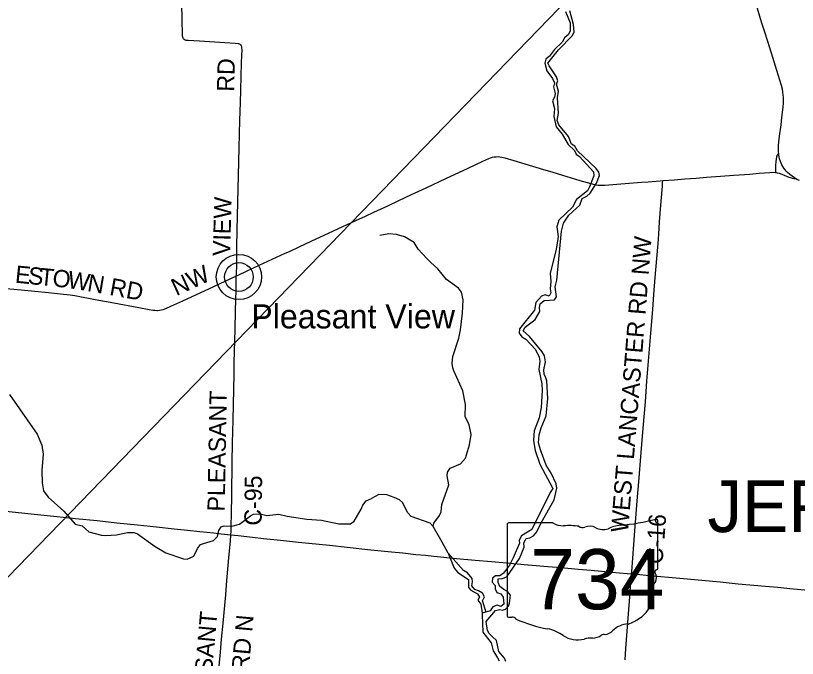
# Model space of a CAD drawing. Extents: x -49 to -8.2, y 9.4 to 23.5.
# Drawn here: x -41.967 to -40.683, y 18.399 to 19.456 of the extents above; entities that cross this region are included whole.
import ezdxf

# ---------------------------------------------------------------- set-up
doc = ezdxf.new("R2010")
doc.units = 0
for name, color, linetype in [('GM_X_County_Road', 7, 'Continuous'), ('GM_X_County_Road_Text', 7, 'Continuous'), ('GM_X_Major_River', 7, 'Continuous'), ('GM_X_Minor_River', 7, 'Continuous'), ('GM_X_State_Route', 7, 'Continuous'), ('GM_X_State_Shield', 7, 'Continuous'), ('GM_X_Township_Text', 7, 'Continuous'), ('GM_X_Unincorporated', 7, 'Continuous'), ('GM_X_Unincorporated_Text', 7, 'Continuous'), ('SC_Scratch1', 7, 'Continuous')]:
    doc.layers.add(name, color=color, linetype=linetype)

msp = doc.modelspace()

# ---------------------------------------------------------------- linework, layer by layer
at = {"layer": 'GM_X_County_Road'}
for points in [[(-41.6048, 19.0281), (-41.6042, 19.0488), (-41.6038, 19.0767), (-41.6027, 19.1264), (-41.6011, 19.1932), (-41.6, 19.2382), (-41.5994, 19.2615), (-41.599, 19.2833), (-41.5982, 19.3128), (-41.5976, 19.3329), (-41.5969, 19.3562), (-41.5962, 19.378), (-41.5958, 19.3904), (-41.5955, 19.3997), (-41.5956, 19.4027), (-41.5958, 19.4042), (-41.5963, 19.4056), (-41.5969, 19.4069), (-41.5979, 19.4079), (-41.5991, 19.4087), (-41.6005, 19.4092), (-41.602, 19.4095), (-41.6066, 19.41), (-41.6236, 19.411), (-41.6655, 19.4135), (-41.6841, 19.4146), (-41.6857, 19.4147), (-41.6873, 19.415), (-41.6888, 19.4155), (-41.6903, 19.4163), (-41.6915, 19.4174), (-41.6924, 19.4188), (-41.6929, 19.4203), (-41.6932, 19.4219), (-41.6934, 19.4251), (-41.6937, 19.4484), (-41.6946, 19.4763)], [(-40.7186, 19.198), (-40.7186, 19.2018), (-40.7186, 19.2049), (-40.7184, 19.2095), (-40.7179, 19.2157), (-40.7169, 19.2234), (-40.7165, 19.2252), (-40.7162, 19.2264), (-40.7155, 19.2276), (-40.7148, 19.2284), (-40.7138, 19.2292)], [(-41.6048, 19.0281), (-41.5996, 19.0305), (-41.5671, 19.0454), (-41.5247, 19.0651), (-41.5177, 19.0683), (-41.5015, 19.0758), (-41.4817, 19.085), (-41.445, 19.1019), (-41.4084, 19.1189), (-41.3929, 19.1261), (-41.3788, 19.1326), (-41.3562, 19.143), (-41.3379, 19.1516), (-41.3169, 19.1616), (-41.293, 19.1728), (-41.2605, 19.1879), (-41.2239, 19.205), (-41.2001, 19.2163), (-41.1901, 19.2207), (-41.1872, 19.2218), (-41.1842, 19.2228), (-41.1811, 19.2235), (-41.178, 19.2238), (-41.1748, 19.2239), (-41.1717, 19.2237), (-41.1686, 19.2232), (-41.164, 19.2222), (-41.1491, 19.2178), (-41.1, 19.2029), (-41.0866, 19.1988), (-41.0688, 19.1934), (-41.0405, 19.1849), (-41.0226, 19.1797), (-41.0166, 19.1781), (-41.0136, 19.1775), (-41.0106, 19.1772), (-41.0059, 19.1771), (-40.9997, 19.1773), (-40.9796, 19.1789), (-40.9595, 19.1804), (-40.9393, 19.1819), (-40.9285, 19.1828), (-40.9084, 19.1842), (-40.904, 19.1846)], [(-40.904, 19.1846), (-40.8851, 19.1859), (-40.8681, 19.1872), (-40.8495, 19.1888), (-40.8324, 19.1901), (-40.8092, 19.1918), (-40.7875, 19.1934), (-40.7612, 19.1954), (-40.7457, 19.1966), (-40.7286, 19.1979), (-40.7224, 19.1982), (-40.7193, 19.1981), (-40.7186, 19.198)], [(-40.7186, 19.198), (-40.7177, 19.1979), (-40.7161, 19.1976), (-40.7131, 19.1968), (-40.7087, 19.1951), (-40.6972, 19.1904), (-40.6942, 19.1894), (-40.6919, 19.1887), (-40.6888, 19.1881), (-40.6863, 19.1878)], [(-40.9556, 18.5385), (-40.9553, 18.5425), (-40.9535, 18.5642), (-40.9499, 18.6091), (-40.9478, 18.6369), (-40.9461, 18.6586), (-40.9436, 18.6895), (-40.9396, 18.7375), (-40.9363, 18.7778), (-40.9329, 18.8211), (-40.9302, 18.8551), (-40.9281, 18.8815), (-40.9259, 18.9078), (-40.9239, 18.9341), (-40.9208, 18.9728), (-40.9189, 18.9976), (-40.9168, 19.0254), (-40.9142, 19.0564), (-40.9121, 19.0811), (-40.911, 19.0966), (-40.9095, 19.1167), (-40.9084, 19.1307), (-40.9068, 19.1508), (-40.9049, 19.1755), (-40.9045, 19.1802), (-40.904, 19.1846)], [(-41.9892, 19.0078), (-41.9583, 19.0049), (-41.9134, 19.0006), (-41.8887, 18.9981), (-41.8779, 18.9968), (-41.8702, 18.9955), (-41.8366, 18.9892), (-41.8061, 18.9835), (-41.7648, 18.9758), (-41.748, 18.9727), (-41.7419, 18.9717), (-41.7388, 18.9714), (-41.7357, 18.9712), (-41.7342, 18.9713), (-41.7312, 18.9716), (-41.7282, 18.9721), (-41.7252, 18.973), (-41.7209, 18.9745), (-41.7123, 18.9782), (-41.6925, 18.9872), (-41.6418, 19.0108), (-41.6221, 19.02), (-41.6048, 19.0281)], [(-41.6138, 18.6026), (-41.6134, 18.6077), (-41.6132, 18.617), (-41.6128, 18.6372), (-41.6125, 18.6683), (-41.6117, 18.7211), (-41.6111, 18.7537), (-41.6103, 18.791), (-41.6086, 18.8671), (-41.6082, 18.8857), (-41.607, 18.9401), (-41.6062, 18.9711), (-41.6053, 19.0053), (-41.6049, 19.027), (-41.6048, 19.0281)], [(-41.6386, 18.3226), (-41.6375, 18.3354), (-41.6339, 18.3756), (-41.6309, 18.4097), (-41.629, 18.4313), (-41.6266, 18.4576), (-41.6223, 18.504), (-41.6203, 18.5272), (-41.6165, 18.5706), (-41.6145, 18.5922), (-41.6138, 18.6026)], [(-40.9663, 18.397), (-40.9649, 18.4156), (-40.9606, 18.4728), (-40.9584, 18.5007), (-40.9571, 18.5177), (-40.9556, 18.5385)]]:
    msp.add_lwpolyline(points, dxfattribs=at)
at = {"layer": 'GM_X_Major_River'}
for points in [[(-41.0642, 19.4627), (-41.0565, 19.4439), (-41.0566, 19.4308), (-41.0591, 19.4248), (-41.0655, 19.4191), (-41.0694, 19.4119), (-41.0823, 19.4002), (-41.0903, 19.3889), (-41.0964, 19.3841), (-41.0979, 19.3773), (-41.095, 19.3652), (-41.0852, 19.3522), (-41.0824, 19.3454), (-41.0836, 19.3389), (-41.081, 19.3279), (-41.0819, 19.3218), (-41.0856, 19.3158), (-41.082, 19.3031), (-41.0834, 19.2898), (-41.0795, 19.2731), (-41.0694, 19.2611), (-41.0598, 19.244), (-41.0491, 19.234), (-41.0468, 19.2278), (-41.0408, 19.2241), (-41.0182, 19.1992), (-41.0177, 19.1925), (-41.0246, 19.1742), (-41.0277, 19.1677), (-41.0459, 19.1534), (-41.0526, 19.1409), (-41.0752, 19.1198), (-41.0781, 19.1086), (-41.0759, 19.0925), (-41.0795, 19.0714), (-41.0895, 19.0322), (-41.0883, 19.0187), (-41.0893, 19.0066), (-41.088, 19.0001), (-41.0908, 18.9945), (-41.0977, 18.9966), (-41.1037, 18.9949), (-41.113, 18.9843), (-41.115, 18.9718), (-41.1396, 18.9412), (-41.14, 18.934), (-41.1357, 18.9279), (-41.1295, 18.9241), (-41.1133, 18.907), (-41.1071, 18.8944), (-41.1062, 18.8881), (-41.1078, 18.8743), (-41.1031, 18.8506), (-41.1024, 18.8394), (-41.1041, 18.8117), (-41.1074, 18.7948), (-41.1153, 18.7734), (-41.1165, 18.7585), (-41.1163, 18.7535), (-41.1138, 18.741), (-41.1061, 18.7188), (-41.0849, 18.6788), (-41.0895, 18.672), (-41.1194, 18.6113), (-41.1366, 18.6006), (-41.1401, 18.5938), (-41.1399, 18.589), (-41.1499, 18.5646), (-41.156, 18.5529), (-41.1659, 18.5393), (-41.1722, 18.5351), (-41.1788, 18.535), (-41.1839, 18.531), (-41.1845, 18.5249), (-41.1796, 18.5194), (-41.1797, 18.5139), (-41.1771, 18.5078), (-41.1703, 18.5057), (-41.1667, 18.5002), (-41.1654, 18.4884), (-41.1704, 18.4847), (-41.1762, 18.487), (-41.1832, 18.4842), (-41.1878, 18.4775), (-41.2011, 18.4735)], [(-41.0957, 18.7172), (-41.1054, 18.7419), (-41.1082, 18.7539), (-41.1074, 18.7669), (-41.1043, 18.7783), (-41.0959, 18.798), (-41.0931, 18.8264), (-41.0946, 18.8557), (-41.0965, 18.8604), (-41.0989, 18.8663), (-41.0998, 18.8737), (-41.0969, 18.8868), (-41.0987, 18.8964), (-41.1025, 18.9031), (-41.1234, 18.9282), (-41.1337, 18.9378), (-41.1301, 18.9438), (-41.1252, 18.9476), (-41.1187, 18.9523), (-41.114, 18.9561), (-41.1061, 18.9695), (-41.107, 18.9758), (-41.1055, 18.982), (-41.0992, 18.9873), (-41.0822, 18.9887), (-41.0791, 18.9937), (-41.0809, 19.0098), (-41.0784, 19.0208), (-41.0704, 19.1014), (-41.0675, 19.1148), (-41.0585, 19.1279), (-41.0407, 19.1441), (-41.0366, 19.1551), (-41.0289, 19.1588), (-41.0233, 19.1639), (-41.0134, 19.1804), (-41.0082, 19.1932), (-41.0095, 19.1982), (-41.0137, 19.2043), (-41.0444, 19.2336), (-41.0487, 19.2409), (-41.0541, 19.2443), (-41.0594, 19.2572), (-41.075, 19.2761), (-41.0776, 19.2831), (-41.0766, 19.2896), (-41.0755, 19.2954), (-41.077, 19.3207), (-41.0753, 19.3317), (-41.0786, 19.3431), (-41.0767, 19.3486), (-41.0789, 19.3552), (-41.0911, 19.3729), (-41.093, 19.3777), (-41.0755, 19.3994), (-41.0524, 19.423), (-41.0496, 19.4291), (-41.0507, 19.4412), (-41.0568, 19.4636)], [(-41.1619, 18.3945), (-41.1644, 18.3997), (-41.1736, 18.4109), (-41.1775, 18.4286), (-41.1841, 18.435), (-41.1897, 18.4404), (-41.1921, 18.4451), (-41.1945, 18.4603), (-41.1789, 18.4779), (-41.1725, 18.4797), (-41.1676, 18.4788), (-41.1628, 18.4801), (-41.1579, 18.4854), (-41.1559, 18.4903), (-41.1542, 18.5032), (-41.1593, 18.5096), (-41.1655, 18.5127), (-41.1717, 18.5177), (-41.1747, 18.5241), (-41.1749, 18.53), (-41.1682, 18.5305), (-41.1606, 18.5335), (-41.1399, 18.5638), (-41.132, 18.5821), (-41.1325, 18.5895), (-41.1285, 18.5965), (-41.1225, 18.5977), (-41.1164, 18.6008), (-41.1109, 18.6076), (-41.1043, 18.6222), (-41.0828, 18.6599), (-41.0781, 18.6792), (-41.0796, 18.6864), (-41.0876, 18.7039), (-41.0957, 18.7172)], [(-41.2011, 18.4735), (-41.2009, 18.4708), (-41.1997, 18.4425), (-41.1862, 18.425), (-41.1827, 18.4119), (-41.1789, 18.4056), (-41.1759, 18.4001), (-41.1733, 18.3952)]]:
    msp.add_lwpolyline(points, dxfattribs=at)
at = {"layer": 'GM_X_Minor_River'}
for points in [[(-41.2814, 18.6161), (-41.2804, 18.6219), (-41.2708, 18.6342), (-41.2685, 18.6401), (-41.2672, 18.6522), (-41.2558, 18.6848), (-41.2586, 18.6996), (-41.2578, 18.7057), (-41.2538, 18.7119), (-41.2365, 18.7194), (-41.2285, 18.7287), (-41.2218, 18.7502), (-41.2192, 18.7673), (-41.2226, 18.7834), (-41.2287, 18.7969), (-41.2281, 18.8169), (-41.2327, 18.8393), (-41.2475, 18.8718), (-41.2491, 18.8767), (-41.2504, 18.8841), (-41.2492, 18.8955), (-41.2394, 18.9254), (-41.2363, 18.9394), (-41.2331, 18.9669), (-41.2321, 18.9887), (-41.235, 19.0012), (-41.2399, 19.0077), (-41.2594, 19.022), (-41.2736, 19.0396), (-41.2851, 19.0502), (-41.2921, 19.0565), (-41.306, 19.072), (-41.3126, 19.0826), (-41.3288, 19.0924), (-41.3419, 19.0958), (-41.3544, 19.0972), (-41.3689, 19.0945)], [(-41.9773, 18.833), (-41.9319, 18.7678), (-41.9245, 18.7497), (-41.9224, 18.7351), (-41.9246, 18.7082), (-41.924, 18.6879), (-41.9215, 18.6747), (-41.9138, 18.6646), (-41.8885, 18.6416), (-41.8698, 18.62), (-41.8581, 18.6172), (-41.847, 18.6074), (-41.8261, 18.6017), (-41.8194, 18.6012), (-41.8016, 18.6026), (-41.7834, 18.6064), (-41.7727, 18.6061), (-41.7674, 18.604), (-41.7383, 18.5834), (-41.7204, 18.5731), (-41.6915, 18.5632), (-41.6855, 18.5627), (-41.6749, 18.5672), (-41.6687, 18.5802), (-41.6635, 18.5864), (-41.6588, 18.5885), (-41.6421, 18.593), (-41.636, 18.5996), (-41.6336, 18.6095), (-41.6296, 18.6157), (-41.6248, 18.6175), (-41.6123, 18.6165), (-41.5998, 18.6201), (-41.5815, 18.6336), (-41.5766, 18.6362), (-41.5658, 18.6369), (-41.5549, 18.6341), (-41.535, 18.6364), (-41.5214, 18.633), (-41.4889, 18.6283), (-41.4647, 18.6266), (-41.4367, 18.6208), (-41.4171, 18.6206), (-41.4114, 18.6251), (-41.4, 18.6445), (-41.3969, 18.6515), (-41.3917, 18.6583), (-41.3828, 18.6623)], [(-41.2566, 18.5721), (-41.2669, 18.5904), (-41.2814, 18.6161), (-41.2862, 18.6218), (-41.3174, 18.6324), (-41.3229, 18.6385), (-41.3321, 18.6558), (-41.337, 18.6598), (-41.3455, 18.664), (-41.3577, 18.6682), (-41.371, 18.6685), (-41.3828, 18.6623)], [(-41.1945, 18.4756), (-41.2004, 18.4939), (-41.1972, 18.5007), (-41.2003, 18.5066), (-41.2068, 18.5103), (-41.2132, 18.5129), (-41.2179, 18.5185), (-41.2167, 18.5253), (-41.2176, 18.5306), (-41.2252, 18.5403), (-41.2319, 18.5441), (-41.2566, 18.5721)], [(-41.2566, 18.5721), (-41.2467, 18.5476), (-41.2412, 18.5406), (-41.2233, 18.5291), (-41.2236, 18.5162), (-41.2196, 18.5113), (-41.2085, 18.5053), (-41.2053, 18.4998), (-41.2082, 18.4949), (-41.2033, 18.4884), (-41.2011, 18.4735)]]:
    msp.add_lwpolyline(points, dxfattribs=at)
at = {"layer": 'GM_X_State_Route'}
for points in [[(-40.6798, 19.1845), (-40.684, 19.1866), (-40.6863, 19.1878), (-40.6881, 19.189), (-40.6919, 19.1916), (-40.6956, 19.1946), (-40.6991, 19.1977), (-40.7013, 19.1999), (-40.7033, 19.2023), (-40.7052, 19.2049), (-40.7069, 19.2075), (-40.7084, 19.2103), (-40.7097, 19.2131), (-40.7109, 19.216), (-40.7123, 19.2205), (-40.713, 19.2236), (-40.7135, 19.2266), (-40.7138, 19.2292), (-40.714, 19.2313), (-40.7141, 19.236), (-40.7139, 19.2422), (-40.7135, 19.2485), (-40.7124, 19.2577), (-40.7099, 19.2762), (-40.7084, 19.2885), (-40.7065, 19.3055), (-40.7059, 19.3117), (-40.7057, 19.3163), (-40.7058, 19.321), (-40.7062, 19.3256), (-40.7068, 19.3301), (-40.7077, 19.3347), (-40.7093, 19.3407), (-40.7147, 19.3585), (-40.7235, 19.3867), (-40.7286, 19.403), (-40.7361, 19.4267), (-40.7407, 19.4415), (-40.7435, 19.4504), (-40.7499, 19.4712)], [(-41.9942, 18.6422), (-41.937, 18.6364), (-41.9046, 18.6331), (-41.8845, 18.631), (-41.869, 18.6294), (-41.8335, 18.6258), (-41.801, 18.6224), (-41.767, 18.6188), (-41.7361, 18.6157), (-41.7068, 18.6126), (-41.6851, 18.6104), (-41.665, 18.6081), (-41.6419, 18.6055), (-41.6295, 18.6043), (-41.6138, 18.6026), (-41.6017, 18.6012), (-41.5785, 18.5987), (-41.56, 18.5967), (-41.5322, 18.5938), (-41.5028, 18.5906), (-41.4518, 18.5853), (-41.4225, 18.5822), (-41.3839, 18.578), (-41.3499, 18.5745), (-41.3313, 18.5727), (-41.3097, 18.5704), (-41.2942, 18.5689), (-41.2802, 18.5675)], [(-41.2802, 18.5675), (-41.2695, 18.5664), (-41.2432, 18.5637), (-41.2122, 18.561), (-41.1859, 18.5588), (-41.1612, 18.5565), (-41.1259, 18.5534)], [(-41.1259, 18.5534), (-41.1256, 18.5534), (-41.093, 18.5505), (-41.0714, 18.5486), (-41.0435, 18.5463), (-41.0219, 18.5444), (-40.9878, 18.5414), (-40.963, 18.5391), (-40.9556, 18.5385), (-40.9476, 18.5377), (-40.9259, 18.5358), (-40.8764, 18.5312), (-40.8099, 18.5251), (-40.7805, 18.5222), (-40.7356, 18.5181), (-40.7155, 18.5163), (-40.6954, 18.5144), (-40.6412, 18.5094)]]:
    msp.add_lwpolyline(points, dxfattribs=at)
at = {"layer": 'GM_X_State_Shield'}
for p, q in [((-41.0849, 18.6222), (-41.1573, 18.6222)), ((-40.9126, 18.5474), (-40.9126, 18.6259)), ((-41.1598, 18.6196), (-41.1598, 18.4695)), ((-40.9126, 18.5474), (-40.9126, 18.5474))]:
    msp.add_line(p, q, dxfattribs=at)
for centre, major_axis, start_param, end_param in [((-41.1569, 18.6199), (0.00286, 0), 1.712693, 3.28349), ((-41.0677, 18.6396), (0.0278, 0), 4.042523, 4.731795), ((-41.0006, 18.8268), (0.2621, 0), 4.814394, 5.042369), ((-40.9153, 18.6262), (0.00275, 0), 6.141152, 7.989035), ((-41.0585, 18.5379), (0.0997, 0), 1.404758, 1.657858), ((-41.0359, 18.6207), (0.00801, 0), 3.836095, 5.185415), ((-41.0241, 18.6033), (0.0167, 0), 0.950623, 2.079405), ((-41.0026, 18.6271), (0.02, 0), 4.081561, 5.145723), ((-40.9672, 18.5763), (0.0527, 0), 1.699011, 2.107814), ((-40.9155, 18.5471), (0.00294, 0), 5.05454, 6.418171), ((-40.9132, 18.5416), (0.00426, 0), 1.883978, 3.671073), ((-40.9403, 18.5317), (0.0256, 0), 5.934695, 6.695948), ((-40.9027, 18.5145), (0.0186, 0), 2.387724, 3.262537), ((-40.9859, 18.5045), (0.0656, 0), 5.101752, 6.440018), ((-41.1569, 18.4692), (0.00289, 0), 3.00124, 4.508301), ((-41.1565, 18.4845), (0.022, 0), 4.665946, 4.897461), ((-41.152, 18.4608), (0.00795, 0), 0.519207, 1.627899), ((-41.0516, 18.5957), (0.1893, 0), 4.195997, 4.488961), ((-40.9583, 18.4274), (0.0359, 0), 1.647645, 2.488434), ((-41.108, 18.4021), (0.0592, 0), 0.823519, 1.323587), ((-41.0038, 18.455), (0.0212, 0), 4.937069, 5.64225), ((-41.044, 18.4601), (0.0376, 0), 4.026481, 4.996735), ((-41.0223, 18.4082), (0.0309, 0), 1.495662, 1.94098), ((-41.0195, 18.4489), (0.02, 0), 4.691044, 5.507374), ((-41.0014, 18.4343), (0.00564, 0), 1.147584, 2.315152)]:
    msp.add_ellipse(centre, major_axis=major_axis, ratio=0.8, start_param=start_param, end_param=end_param, dxfattribs=at)
at = {"layer": 'GM_X_Unincorporated'}
for radius in [0.0372, 0.0236]:
    msp.add_circle((-41.6006, 19.0262), radius, dxfattribs=at)
at = {"layer": 'SC_Scratch1'}
msp.add_line((-48.2943, 12.0149), (-38.2371, 22.3973), dxfattribs=at)

# ---------------------------------------------------------------- texts
at = {"layer": 'GM_X_County_Road_Text'}
for s, height, rotation, p in [('RD', 0.02841, 88.5055, (-41.6085, 19.3304)), ('VIEW', 0.02841, 88.4233, (-41.6152, 19.0603)), ('WEST LANCASTER RD NW', 0.028409, 85.4239, (-40.9614, 18.6056)), ('NW', 0.02841, 24.7519, (-41.7034, 18.9945)), ('E', 0.0284, 354.3882, (-41.9692, 19.017)), ('S', 0.0284, 354.3892, (-41.9481, 19.0149)), ('T', 0.0284, 354.3854, (-41.929, 19.013)), ('O', 0.0284, 354.0076, (-41.9079, 19.0109)), ('W', 0.0284, 351.0046, (-41.8834, 19.0084)), ('N', 0.0284, 350.3374, (-41.851, 19.0032)), ('RD', 0.02841, 349.5626, (-41.8145, 18.9969)), ('PLEASANT', 0.02841, 88.9267, (-41.624, 18.6406)), ('C-95', 0.02841, 89.3152, (-41.5634, 18.6175)), ('C-16', 0.02841, 85.5381, (-40.9048, 18.5535)), ('PLEASANT', 0.02841, 84.9016, (-41.6535, 18.2777)), ('VIEW RD N', 0.02841, 84.9007, (-41.5941, 18.27))]:
    msp.add_text(s, height=height, rotation=rotation, dxfattribs=at).set_placement(p)
at = {"layer": 'GM_X_State_Shield'}
msp.add_text('734', height=0.09888, dxfattribs=at).set_placement((-41.122, 18.4801))
at = {"layer": 'GM_X_Township_Text'}
msp.add_text('JEFFERSON', height=0.08523, rotation=0, dxfattribs=at).set_placement((-40.8309, 18.6069))
at = {"layer": 'GM_X_Unincorporated_Text'}
msp.add_text('Pleasant View', height=0.039489, rotation=0, dxfattribs=at).set_placement((-41.5803, 18.9417))

doc.saveas('drawing.dxf')
